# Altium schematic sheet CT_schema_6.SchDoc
size 302 x 256 mm
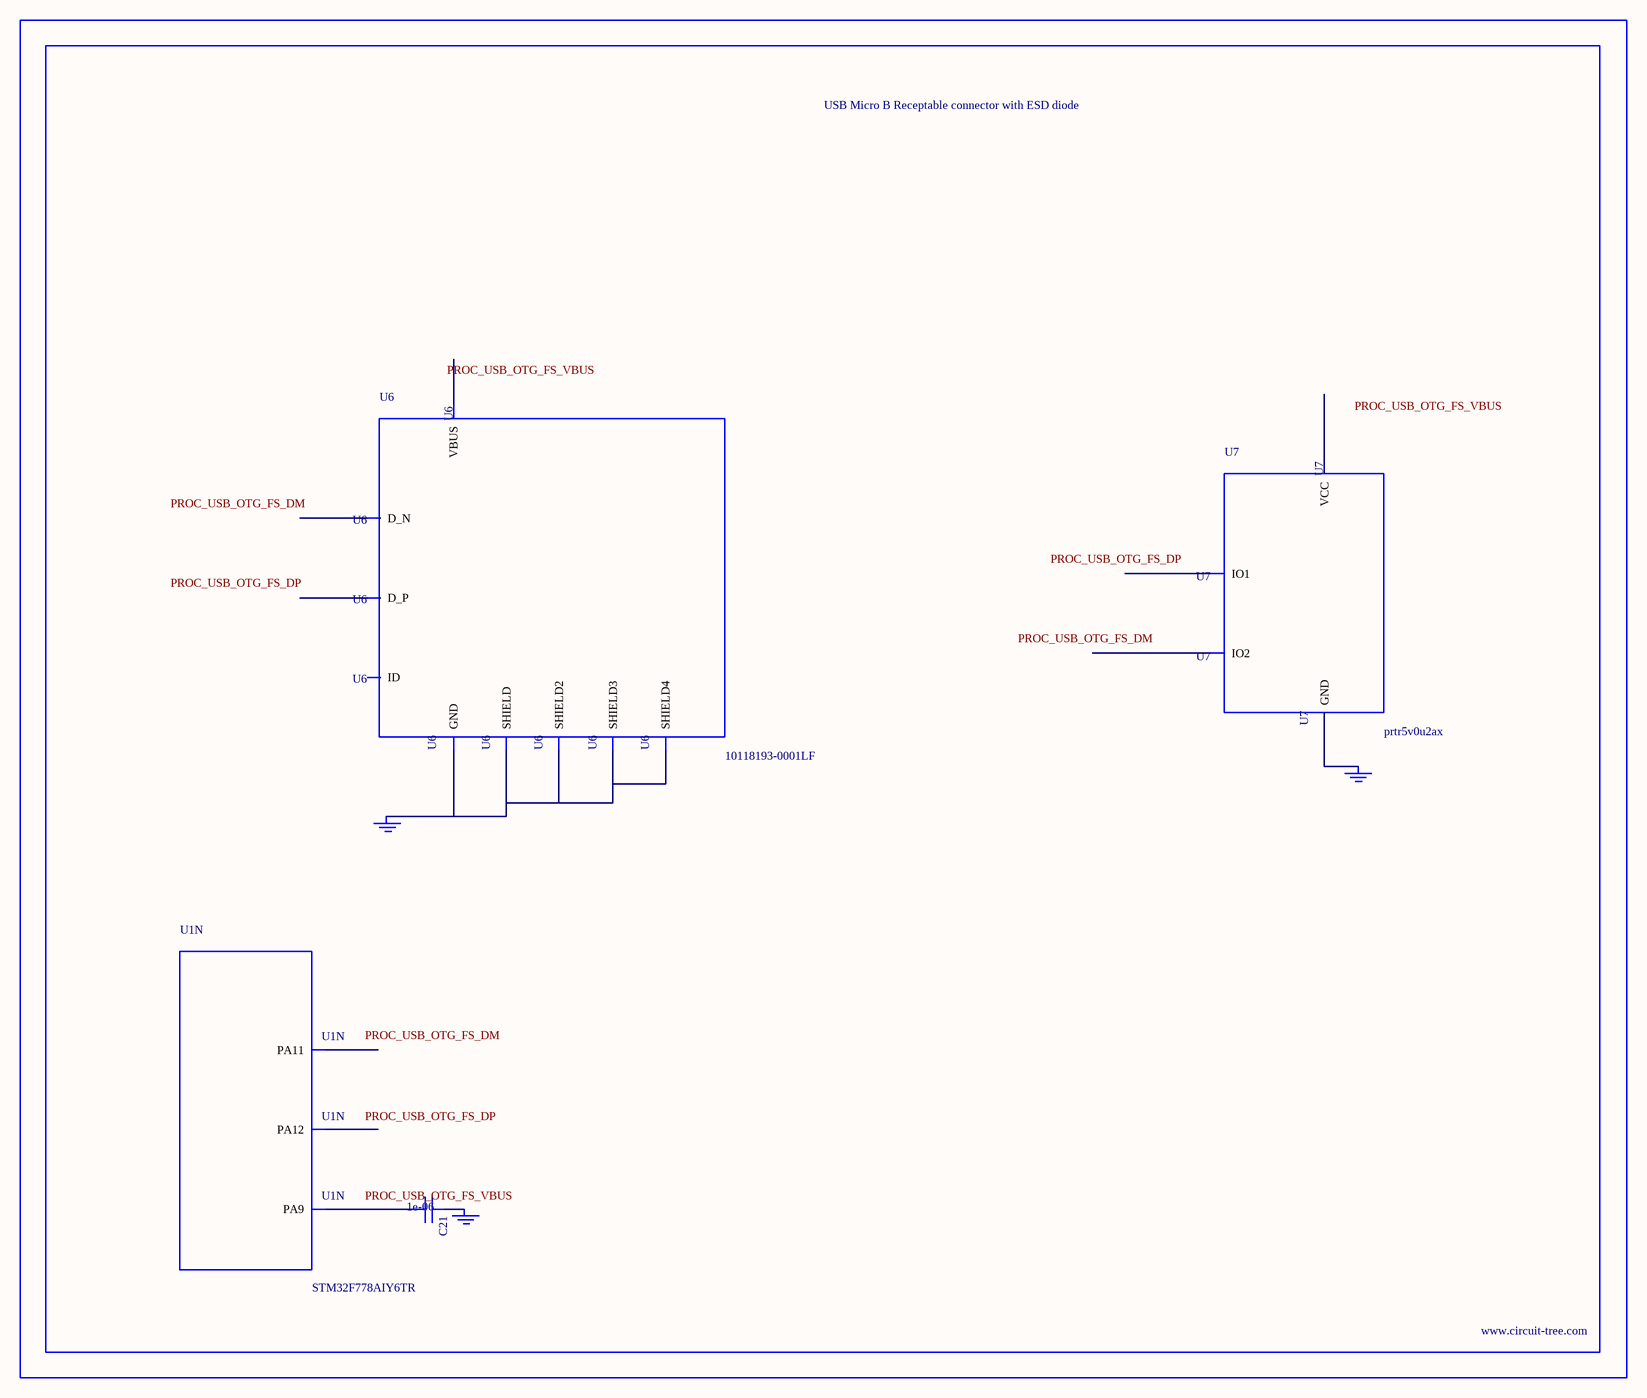
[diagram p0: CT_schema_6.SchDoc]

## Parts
BORDER5  (no value)
C21  1e-06  [C0603]
GND_INSTANCE_5_0  (no value)
GND_INSTANCE_5_1  (no value)
GND_INSTANCE_5_2  (no value)
U1  STM32F778AIY6TR  [WLCSP180]  (part N of 15)
U6  10118193-0001LF  [FCI_10118193-0001LF]
U7  prtr5v0u2ax  [SOT143B]

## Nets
NetC21_1: C21.1 GND_INSTANCE_5_1.0(GND)
NetC21_2: C21.2 U1.F4(PA9)
NetGND_INSTANCE_5_0_0: GND_INSTANCE_5_0.0(GND) U6.5(GND) U6.6(SHIELD) U6.7(SHIELD2) U6.8(SHIELD3) U6.9(SHIELD4)
NetGND_INSTANCE_5_2_0: GND_INSTANCE_5_2.0(GND) U7.1(GND)

Not connected (* = marked no-connect by the designer): U1 D1(PA12) E3(PA11); U6 1(VBUS) 2(D_N) 3(D_P) 4(ID); U7 2(IO1) 3(IO2) 4(VCC)

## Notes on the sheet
- Labels drawn without touching a wire or pin: PROC_USB_OTG_FS_DM, PROC_USB_OTG_FS_DP, PROC_USB_OTG_FS_VBUS

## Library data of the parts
BORDER5 = BORDER_PAGE5
C21 = C0603C105K3RACTU
GND_INSTANCE_5_0-GND_INSTANCE_5_2 = GND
